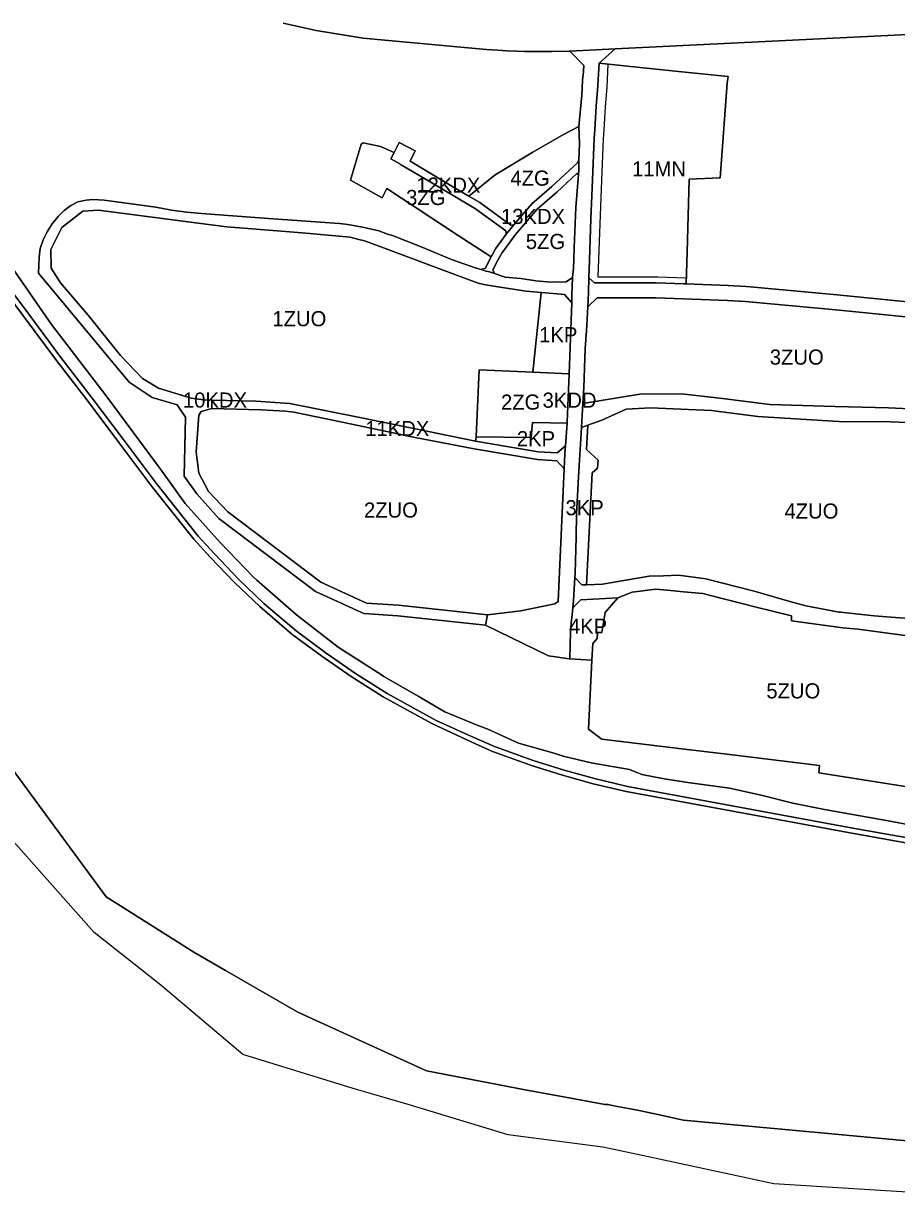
# Model space of a CAD drawing. Extents: x -300162 to -296646, y 29434 to 30761.
# Drawn here: x -298006 to -297429, y 29437 to 30215 of the extents above; entities that cross this region are included whole.
import ezdxf

# ---------------------------------------------------------------- set-up
doc = ezdxf.new("R2010")
doc.units = 0
for name, color, linetype in [('linie_rozgraniczajace', 7, 'Continuous'), ('linie_zabudowy_nieprzekraczalne', 7, 'Continuous'), ('oznaczenia_przeznaczen', 7, 'Continuous')]:
    doc.layers.add(name, color=color, linetype=linetype)

msp = doc.modelspace()

# ---------------------------------------------------------------- linework, layer by layer
at = {"layer": 'linie_rozgraniczajace'}
for points in [[(-297834.429, 30215.074), (-297812.629, 30210.261), (-297781.644, 30205.237), (-297733.747, 30200.685), (-297712.203, 30198.696), (-297699.897, 30197.649), (-297692.484, 30197.175), (-297686.228, 30196.858), (-297679.912, 30196.588), (-297674.636, 30196.456), (-297668.374, 30196.328), (-297662.056, 30196.303), (-297656.737, 30196.33), (-297645.247, 30196.578), (-297644.846, 30196.597), (-297635.515, 30186.993), (-297635.79, 30183.19), (-297636.55, 30177.47), (-297636.85, 30167.52), (-297638.96, 30146.68), (-297648.94, 30141.41), (-297669.26, 30129.69), (-297694.28, 30114.71), (-297711.654, 30100.692), (-297720.597, 30106.029), (-297737.288, 30115.896), (-297750.558, 30123.718), (-297747.058, 30130.668), (-297757.776, 30136.065), (-297761.02, 30129.622), (-297770.095, 30133.601), (-297781.551, 30136.015), (-297782.84, 30135.06), (-297790.02, 30111.23), (-297768.98, 30099.51), (-297765.93, 30105.72), (-297718.66, 30074.65), (-297696.978, 30060.544), (-297697.129, 30060.276), (-297700.683, 30053.135), (-297703.477, 30052.076), (-297706.72, 30053.03), (-297723.04, 30058.87), (-297743.15, 30067.08), (-297762.08, 30074.63), (-297765.49, 30075.52), (-297771.26, 30077.67), (-297780.95, 30080.01), (-297790.41, 30081.74), (-297793.425, 30082.092), (-297796.978, 30082.507), (-297797, 30082.51), (-297800.47, 30082.73), (-297844.24, 30085.97), (-297888.43, 30089.19), (-297898.28, 30090.18), (-297908.23, 30091.35), (-297918.66, 30093.495), (-297952.956, 30098.005), (-297960.405, 30098.422), (-297964.869, 30098.134), (-297970.39, 30097.009), (-297974.977, 30094.482), (-297979.292, 30091.17), (-297983.199, 30087.262), (-297987.293, 30082.444), (-297990.481, 30077.137), (-297993.19, 30071.771)], [(-297403, 30208.4), (-297614.92, 30198.015), (-297644.846, 30196.597), (-297645.247, 30196.578), (-297656.737, 30196.33), (-297662.056, 30196.303), (-297668.374, 30196.328), (-297674.636, 30196.456), (-297679.912, 30196.588), (-297686.228, 30196.858), (-297692.484, 30197.175), (-297699.897, 30197.649), (-297712.203, 30198.696), (-297733.747, 30200.685), (-297781.644, 30205.237), (-297812.629, 30210.261), (-297834.429, 30215.074)], [(-297408.4, 30029.57), (-297468.03, 30035.37), (-297527.92, 30041.03), (-297540.19, 30041.66), (-297567.956, 30042.662), (-297567.322, 30063.537), (-297565.85, 30111.98), (-297545.398, 30112.737), (-297540.72, 30175.38), (-297540.196, 30179.766), (-297570.75, 30182.96), (-297592.07, 30185.13), (-297625.44, 30188.57), (-297614.92, 30198.015), (-297403, 30208.4)], [(-297343.9, 29437.13), (-297510, 29447.37), (-297600.03, 29466.88), (-297623.03, 29471.65), (-297685.72, 29479.9), (-297751.84, 29500), (-297788.27, 29510.52), (-297861.05, 29532.95), (-297915.32, 29578.84), (-297959.37, 29613.67), (-298021.78, 29683.83), (-298089.26, 29768.65), (-298133.84, 29820.72), (-298172.27, 29865.83), (-298208.12, 29903.83), (-298240, 29938), (-298289.95, 30000), (-298295.47, 30008.63), (-298336.46, 30059.03), (-298349.16, 30067.38), (-298382.23, 30086.44), (-298449.27, 30117)], [(-298040.891, 30067.651), (-298006.13, 30021.4), (-297984.968, 29992.847), (-297963.49, 29964.905), (-297943.105, 29937.761), (-297921.249, 29908.659), (-297893.476, 29873.754), (-297882.793, 29861.917), (-297866.885, 29845.287), (-297849.967, 29829.235), (-297828.747, 29811.104), (-297808.797, 29796.409), (-297789.511, 29782.897), (-297768.378, 29769.617), (-297736.1, 29751.89), (-297709.716, 29739.54), (-297696.059, 29733.48), (-297670.242, 29724.237), (-297649.627, 29717.751), (-297629.329, 29712.076), (-297607.483, 29706.861), (-297458.287, 29679.362), (-297372.015, 29663.949)], [(-297372.015, 29663.949), (-297458.287, 29679.362), (-297607.483, 29706.861), (-297629.329, 29712.076), (-297649.627, 29717.751), (-297670.242, 29724.237), (-297696.059, 29733.48), (-297709.716, 29739.54), (-297736.1, 29751.89), (-297768.378, 29769.617), (-297789.511, 29782.897), (-297808.797, 29796.409), (-297828.747, 29811.104), (-297849.967, 29829.235), (-297866.885, 29845.287), (-297882.793, 29861.917), (-297893.476, 29873.754), (-297921.249, 29908.659), (-297943.105, 29937.761), (-297963.49, 29964.905), (-297984.968, 29992.847), (-298006.13, 30021.4), (-298040.891, 30067.651)], [(-297371.4, 29667.394), (-297457.662, 29682.806), (-297606.759, 29710.286), (-297628.451, 29715.465), (-297648.63, 29721.107), (-297669.127, 29727.555), (-297694.758, 29736.732), (-297708.297, 29742.74), (-297733.302, 29753.993), (-297765.58, 29771.72), (-297786.713, 29785), (-297805.999, 29798.512), (-297825.949, 29813.207), (-297847.169, 29831.338), (-297864.088, 29847.39), (-297879.995, 29864.02), (-297890.678, 29875.857), (-297918.452, 29910.762), (-297940.307, 29939.864), (-297960.692, 29967.008), (-297982.17, 29994.95), (-298003.332, 30023.503), (-298038.093, 30069.754)], [(-298038.093, 30069.754), (-298003.332, 30023.503), (-297982.17, 29994.95), (-297960.692, 29967.008), (-297940.307, 29939.864), (-297918.452, 29910.762), (-297890.678, 29875.857), (-297879.995, 29864.02), (-297864.088, 29847.39), (-297847.169, 29831.338), (-297825.949, 29813.207), (-297805.999, 29798.512), (-297786.713, 29785), (-297765.58, 29771.72), (-297733.302, 29753.993), (-297708.297, 29742.74), (-297694.758, 29736.732), (-297669.127, 29727.555), (-297648.63, 29721.107), (-297628.451, 29715.465), (-297606.759, 29710.286), (-297457.662, 29682.806), (-297371.4, 29667.394)], [(-297993.19, 30071.771), (-297995.175, 30066.143), (-297995.888, 30060.319), (-297996.354, 30049.813), (-297936.291, 29977.609), (-297921.057, 29967.524), (-297904.583, 29962.56), (-297899.052, 29954.541), (-297899.953, 29915.429), (-297891.473, 29903.717), (-297876.909, 29887.549), (-297813.085, 29839.287), (-297781.116, 29824.599), (-297758.698, 29823.144), (-297700.599, 29816.952), (-297658.966, 29796.641), (-297645.29, 29794.75), (-297644.746, 29794.714), (-297630.21, 29793.75), (-297632.44, 29748.2), (-297624.429, 29742.106), (-297623.79, 29741.62), (-297568.96, 29734.9), (-297541.11, 29731.54), (-297479.69, 29724.12), (-297480.15, 29719.3), (-297390.88, 29705.09)], [(-297415.28, 29684.09), (-297436.71, 29688.07), (-297476.37, 29695.11), (-297497.44, 29699.34), (-297518.32, 29704.43), (-297539.17, 29709.17), (-297566.8, 29712.96), (-297582.43, 29715.38), (-297597.33, 29718.21), (-297605.44, 29721.39), (-297630.67, 29725.94), (-297649.33, 29730.33), (-297654.52, 29732), (-297678.72, 29738.87), (-297699.07, 29748.16), (-297706.04, 29750.71), (-297727.47, 29759.66), (-297745.16, 29769.96), (-297767.83, 29783.02), (-297769.38, 29784.14), (-297798.04, 29802.45), (-297825.56, 29823.7), (-297851.87, 29846.63), (-297854.09, 29848.73), (-297876.1, 29871.71), (-297899.26, 29897.42), (-297915.63, 29920.03), (-297951.51, 29968.57), (-297987.76, 30015.69), (-298013.94, 30053.73)], [(-298013.94, 30053.73), (-297987.76, 30015.69), (-297951.51, 29968.57), (-297915.63, 29920.03), (-297899.26, 29897.42), (-297876.1, 29871.71), (-297854.09, 29848.73), (-297851.87, 29846.63), (-297825.56, 29823.7), (-297798.04, 29802.45), (-297769.38, 29784.14), (-297767.83, 29783.02), (-297745.16, 29769.96), (-297727.47, 29759.66), (-297706.04, 29750.71), (-297699.07, 29748.16), (-297678.72, 29738.87), (-297654.52, 29732), (-297649.33, 29730.33), (-297630.67, 29725.94), (-297605.44, 29721.39), (-297597.33, 29718.21), (-297582.43, 29715.38), (-297566.8, 29712.96), (-297539.17, 29709.17), (-297518.32, 29704.43), (-297497.44, 29699.34), (-297476.37, 29695.11), (-297436.71, 29688.07), (-297415.28, 29684.09)], [(-297409.365, 30019.617), (-297468.984, 30025.416), (-297528.647, 30031.054), (-297540.627, 30031.669), (-297569.66, 30032.716), (-297587.859, 30033.37), (-297626.691, 30033.37), (-297633.008, 30027.378), (-297632.5, 30036.85), (-297632.22, 30046.56), (-297628.59, 30043.37), (-297587.68, 30043.37), (-297569.3, 30042.71), (-297567.956, 30042.662), (-297540.19, 30041.66), (-297527.92, 30041.03), (-297468.03, 30035.37), (-297408.4, 30029.57)], [(-297415.34, 29959.91), (-297434.09, 29960.59), (-297469.36, 29961.61), (-297512.56, 29962.85), (-297543.82, 29966.76), (-297571.04, 29970), (-297598.57, 29969.77), (-297636.27, 29963.65), (-297635.7, 29974.23), (-297634.61, 29999.89), (-297633.85, 30011.62), (-297633.008, 30027.378), (-297626.691, 30033.37), (-297587.859, 30033.37), (-297569.66, 30032.716), (-297540.627, 30031.669), (-297528.647, 30031.054), (-297468.984, 30025.416), (-297409.365, 30019.617)], [(-297415.84, 29950.68), (-297438.49, 29951.58), (-297462.71, 29951.42), (-297470.73, 29951.9), (-297520.48, 29954.85), (-297551.04, 29958.99), (-297591.43, 29960.58), (-297607.53, 29959.8), (-297623.77, 29952.63), (-297632.953, 29949.162), (-297637.17, 29947.57), (-297636.27, 29963.65), (-297598.57, 29969.77), (-297571.04, 29970), (-297543.82, 29966.76), (-297512.56, 29962.85), (-297469.36, 29961.61), (-297434.09, 29960.59), (-297415.34, 29959.91)], [(-297408.23, 29820.41), (-297429.5, 29822.07), (-297443.54, 29823.17), (-297465.81, 29825.45), (-297466.67, 29825.54), (-297488.86, 29829.64), (-297499.34, 29832.7), (-297515.11, 29837.3), (-297522.95, 29839.34), (-297554.89, 29847.57), (-297573.04, 29850.01), (-297583, 29849.67), (-297592.37, 29849.35), (-297623.24, 29844.15), (-297633.904, 29843.72), (-297630.073, 29917.724), (-297626.507, 29920.883), (-297626.124, 29926.129), (-297633.851, 29933.228), (-297632.953, 29949.162), (-297623.77, 29952.63), (-297607.53, 29959.8), (-297591.43, 29960.58), (-297551.04, 29958.99), (-297520.48, 29954.85), (-297470.73, 29951.9), (-297462.71, 29951.42), (-297438.49, 29951.58), (-297415.84, 29950.68)], [(-297410.06, 29808.44), (-297454.12, 29814.24), (-297464.23, 29815.18), (-297498.34, 29819.73), (-297498.29, 29823.08), (-297521.59, 29828.95), (-297551.87, 29836.59), (-297556.92, 29837.86), (-297569.67, 29839.09), (-297580.44, 29840.12), (-297587.87, 29840.84), (-297603.61, 29838.69), (-297613, 29834.96), (-297637.516, 29833.621), (-297642.968, 29828.375), (-297642.509, 29833.348), (-297641.586, 29848.392), (-297636.864, 29843.601), (-297633.904, 29843.72), (-297623.24, 29844.15), (-297592.37, 29849.35), (-297583, 29849.67), (-297573.04, 29850.01), (-297554.89, 29847.57), (-297522.95, 29839.34), (-297515.11, 29837.3), (-297499.34, 29832.7), (-297488.86, 29829.64), (-297466.67, 29825.54), (-297465.81, 29825.45), (-297443.54, 29823.17), (-297429.5, 29822.07), (-297408.23, 29820.41)], [(-297390.88, 29705.09), (-297480.15, 29719.3), (-297479.69, 29724.12), (-297541.11, 29731.54), (-297568.96, 29734.9), (-297623.79, 29741.62), (-297624.429, 29742.106), (-297632.44, 29748.2), (-297630.21, 29793.75), (-297629.67, 29804.88), (-297626.84, 29808.14), (-297626.45, 29812), (-297623.7, 29812), (-297621.38, 29825.35), (-297613, 29834.96), (-297603.61, 29838.69), (-297587.87, 29840.84), (-297580.44, 29840.12), (-297569.67, 29839.09), (-297556.92, 29837.86), (-297551.87, 29836.59), (-297521.59, 29828.95), (-297498.29, 29823.08), (-297498.34, 29819.73), (-297464.23, 29815.18), (-297454.12, 29814.24), (-297410.06, 29808.44)], [(-298051.094, 29772.591), (-297951.586, 29637.393), (-297893.544, 29600.792), (-297872.694, 29588.579), (-297824.733, 29561.012), (-297739.61, 29522.298), (-297674.457, 29509.694), (-297644.26, 29504.153), (-297621.651, 29500.004), (-297619.547, 29499.97), (-297615.641, 29499.137), (-297605.948, 29497.334), (-297598.927, 29495.944), (-297586.654, 29493.287), (-297569.73, 29489.623), (-297495.404, 29482.761), (-297405.231, 29474.318)], [(-297405.231, 29474.318), (-297495.404, 29482.761), (-297569.73, 29489.623), (-297586.654, 29493.287), (-297598.927, 29495.944), (-297605.948, 29497.334), (-297615.641, 29499.137), (-297619.547, 29499.97), (-297621.651, 29500.004), (-297644.26, 29504.153), (-297674.457, 29509.694), (-297739.61, 29522.298), (-297824.733, 29561.012), (-297872.694, 29588.579), (-297893.544, 29600.792), (-297951.586, 29637.393), (-298051.094, 29772.591)]]:
    msp.add_lwpolyline(points, dxfattribs=at)
for points in [[(-297700.599, 29816.952), (-297699.27, 29823.85), (-297677.31, 29826.46), (-297654.8, 29831.06), (-297652.562, 29832.613), (-297648.695, 29920.41), (-297648.475, 29925.401), (-297648.176, 29930.546), (-297647.795, 29935.537), (-297646.643, 29950.629), (-297646.59, 29951.32), (-297645.4, 29983.24), (-297643.612, 30030.217), (-297643.422, 30035.194), (-297642.98, 30046.81), (-297642.52, 30052.94), (-297642.26, 30059.12), (-297641.96, 30066.73), (-297640.9, 30093.07), (-297639.188, 30115.109), (-297638.98, 30117.79), (-297638.88, 30122.65), (-297638.827, 30124.696), (-297638.55, 30135.45), (-297638.96, 30146.68), (-297636.85, 30167.52), (-297636.55, 30177.47), (-297635.79, 30183.19), (-297635.515, 30186.993), (-297644.846, 30196.597), (-297614.92, 30198.015), (-297625.44, 30188.57), (-297626.625, 30170.623), (-297627.45, 30160.14), (-297628.35, 30144.86), (-297628.78, 30138.9), (-297629.89, 30111.58), (-297630.99, 30085.7), (-297631.92, 30058.43), (-297632.22, 30046.56), (-297632.5, 30036.85), (-297633.008, 30027.378), (-297633.85, 30011.62), (-297634.61, 29999.89), (-297635.7, 29974.23), (-297636.27, 29963.65), (-297637.17, 29947.57), (-297639.2, 29915.1), (-297640.51, 29890.09), (-297640.73, 29875.48), (-297641.43, 29851.24), (-297641.586, 29848.392), (-297642.509, 29833.348), (-297642.968, 29828.375), (-297643.38, 29823.91), (-297643.91, 29818.24), (-297644.43, 29812.77), (-297644.746, 29794.714), (-297645.29, 29794.75), (-297658.966, 29796.641)], [(-297632.22, 30046.56), (-297631.92, 30058.43), (-297630.99, 30085.7), (-297629.89, 30111.58), (-297628.78, 30138.9), (-297628.35, 30144.86), (-297627.45, 30160.14), (-297626.625, 30170.623), (-297625.44, 30188.57), (-297592.07, 30185.13), (-297570.75, 30182.96), (-297540.196, 30179.766), (-297540.72, 30175.38), (-297545.398, 30112.737), (-297565.85, 30111.98), (-297567.322, 30063.537), (-297567.956, 30042.662), (-297569.3, 30042.71), (-297587.68, 30043.37), (-297628.59, 30043.37)], [(-297711.654, 30100.692), (-297694.28, 30114.71), (-297669.26, 30129.69), (-297648.94, 30141.41), (-297638.96, 30146.68), (-297638.55, 30135.45), (-297638.827, 30124.696), (-297639.93, 30122.489), (-297645.007, 30117.865), (-297656.818, 30107.107), (-297670.013, 30095.708), (-297681.919, 30081.704), (-297683.902, 30081.494), (-297704.426, 30096.379)], [(-297790.02, 30111.23), (-297782.84, 30135.06), (-297781.551, 30136.015), (-297770.095, 30133.601), (-297761.02, 30129.622), (-297763.172, 30125.347), (-297757.331, 30121.972), (-297756.93, 30121.67), (-297739.83, 30111.59), (-297723.15, 30101.73), (-297707.18, 30092.2), (-297687.177, 30077.692), (-297686.896, 30075.463), (-297694.043, 30065.76), (-297696.978, 30060.544), (-297718.66, 30074.65), (-297765.93, 30105.72), (-297768.98, 30099.51)], [(-297763.172, 30125.347), (-297761.02, 30129.622), (-297757.776, 30136.065), (-297747.058, 30130.668), (-297750.558, 30123.718), (-297737.288, 30115.896), (-297720.597, 30106.029), (-297711.654, 30100.692), (-297704.426, 30096.379), (-297683.902, 30081.494), (-297681.919, 30081.704), (-297686.896, 30075.463), (-297687.177, 30077.692), (-297707.18, 30092.2), (-297723.15, 30101.73), (-297739.83, 30111.59), (-297756.93, 30121.67), (-297757.331, 30121.972)], [(-297703.477, 30052.076), (-297700.683, 30053.135), (-297697.129, 30060.276), (-297696.978, 30060.544), (-297694.043, 30065.76), (-297686.896, 30075.463), (-297681.919, 30081.704), (-297670.013, 30095.708), (-297656.818, 30107.107), (-297645.007, 30117.865), (-297639.93, 30122.489), (-297638.827, 30124.696), (-297638.88, 30122.65), (-297638.98, 30117.79), (-297639.188, 30115.109), (-297640.113, 30115.56), (-297653.499, 30103.366), (-297666.453, 30092.176), (-297680.835, 30075.26), (-297689.836, 30063.041), (-297692.709, 30057.934), (-297695.699, 30051.928), (-297694.596, 30049.556), (-297698.02, 30050.72), (-297700.23, 30051.12)], [(-297695.699, 30051.928), (-297692.709, 30057.934), (-297689.836, 30063.041), (-297680.835, 30075.26), (-297666.453, 30092.176), (-297653.499, 30103.366), (-297640.113, 30115.56), (-297639.188, 30115.109), (-297640.9, 30093.07), (-297641.96, 30066.73), (-297642.26, 30059.12), (-297642.52, 30052.94), (-297642.98, 30046.81), (-297647.37, 30043.91), (-297657.38, 30043.81), (-297667.42, 30044.64), (-297677.36, 30046.11), (-297687.58, 30047.17), (-297694.596, 30049.556)], [(-297996.354, 30049.813), (-297995.888, 30060.319), (-297995.175, 30066.143), (-297993.19, 30071.771), (-297990.481, 30077.137), (-297987.293, 30082.444), (-297983.199, 30087.262), (-297979.292, 30091.17), (-297974.977, 30094.482), (-297970.39, 30097.009), (-297964.869, 30098.134), (-297960.405, 30098.422), (-297952.956, 30098.005), (-297918.66, 30093.495), (-297908.23, 30091.35), (-297898.28, 30090.18), (-297888.43, 30089.19), (-297844.24, 30085.97), (-297800.47, 30082.73), (-297797, 30082.51), (-297796.978, 30082.507), (-297793.425, 30082.092), (-297790.41, 30081.74), (-297780.95, 30080.01), (-297771.26, 30077.67), (-297765.49, 30075.52), (-297762.08, 30074.63), (-297743.15, 30067.08), (-297723.04, 30058.87), (-297706.72, 30053.03), (-297703.477, 30052.076), (-297700.23, 30051.12), (-297698.02, 30050.72), (-297694.596, 30049.556), (-297687.58, 30047.17), (-297677.36, 30046.11), (-297667.42, 30044.64), (-297657.38, 30043.81), (-297647.37, 30043.91), (-297642.98, 30046.81), (-297643.422, 30035.194), (-297643.612, 30030.217), (-297648.399, 30035.672), (-297650.57, 30035.88), (-297663.918, 30036.992), (-297673.73, 30037.81), (-297692.53, 30040.62), (-297701.73, 30042.3), (-297705.44, 30043.24), (-297730.44, 30052.46), (-297771.54, 30067.75), (-297780.63, 30071.16), (-297785.32, 30072.33), (-297790.1, 30073.53), (-297821.87, 30076.4), (-297871.66, 30080.28), (-297890.64, 30082.75), (-297956.72, 30091.44), (-297966.89, 30090.83), (-297980.77, 30079.92), (-297988.1, 30065.35), (-297987.94, 30053.01), (-297981.81, 30043.29), (-297963.53, 30021.96), (-297941.98, 29995.4), (-297927.48, 29980.1), (-297916.96, 29973.6), (-297895.32, 29967.08), (-297886.98, 29965.97), (-297881.553, 29965.847), (-297881.68, 29960.24), (-297888.6, 29958.36), (-297890.27, 29955.82), (-297891.98, 29931.61), (-297890.23, 29917.39), (-297883.94, 29905.46), (-297871.11, 29891.94), (-297809.47, 29845.33), (-297779.37, 29831.5), (-297758.1, 29830.12), (-297699.27, 29823.85), (-297700.599, 29816.952), (-297758.698, 29823.144), (-297781.116, 29824.599), (-297813.085, 29839.287), (-297876.909, 29887.549), (-297891.473, 29903.717), (-297899.953, 29915.429), (-297899.052, 29954.541), (-297904.583, 29962.56), (-297921.057, 29967.524), (-297936.291, 29977.609)], [(-297988.1, 30065.35), (-297980.77, 30079.92), (-297966.89, 30090.83), (-297956.72, 30091.44), (-297890.64, 30082.75), (-297871.66, 30080.28), (-297821.87, 30076.4), (-297790.1, 30073.53), (-297785.32, 30072.33), (-297780.63, 30071.16), (-297771.54, 30067.75), (-297730.44, 30052.46), (-297705.44, 30043.24), (-297701.73, 30042.3), (-297692.53, 30040.62), (-297673.73, 30037.81), (-297663.918, 30036.992), (-297669.22, 29984.307), (-297704.77, 29985.9), (-297706.75, 29941.41), (-297707.29, 29938.56), (-297756.74, 29948.75), (-297784.87, 29954.55), (-297830.15, 29963.61), (-297852.44, 29965.19), (-297881.553, 29965.847), (-297886.98, 29965.97), (-297895.32, 29967.08), (-297916.96, 29973.6), (-297927.48, 29980.1), (-297941.98, 29995.4), (-297963.53, 30021.96), (-297981.81, 30043.29), (-297987.94, 30053.01)], [(-297669.22, 29984.307), (-297663.918, 30036.992), (-297650.57, 30035.88), (-297648.399, 30035.672), (-297643.612, 30030.217), (-297645.4, 29983.24)], [(-297706.75, 29941.41), (-297704.77, 29985.9), (-297669.22, 29984.307), (-297645.4, 29983.24), (-297646.59, 29951.32), (-297646.643, 29950.629), (-297669.514, 29950.993), (-297670.412, 29941.138)], [(-297881.68, 29960.24), (-297881.553, 29965.847), (-297852.44, 29965.19), (-297830.15, 29963.61), (-297784.87, 29954.55), (-297756.74, 29948.75), (-297707.29, 29938.56), (-297665.76, 29931.662), (-297653.166, 29930.862), (-297647.795, 29935.537), (-297648.176, 29930.546), (-297648.475, 29925.401), (-297648.695, 29920.41), (-297653.465, 29925.718), (-297666.26, 29926.53), (-297708.04, 29933.47), (-297751.71, 29942.04), (-297757.47, 29943.25), (-297799.68, 29952.1), (-297827.51, 29957.72), (-297832.85, 29958.56), (-297849.15, 29959.47)], [(-297891.98, 29931.61), (-297890.27, 29955.82), (-297888.6, 29958.36), (-297881.68, 29960.24), (-297849.15, 29959.47), (-297832.85, 29958.56), (-297827.51, 29957.72), (-297799.68, 29952.1), (-297757.47, 29943.25), (-297751.71, 29942.04), (-297708.04, 29933.47), (-297666.26, 29926.53), (-297653.465, 29925.718), (-297648.695, 29920.41), (-297652.562, 29832.613), (-297654.8, 29831.06), (-297677.31, 29826.46), (-297699.27, 29823.85), (-297758.1, 29830.12), (-297779.37, 29831.5), (-297809.47, 29845.33), (-297871.11, 29891.94), (-297883.94, 29905.46), (-297890.23, 29917.39)], [(-297707.29, 29938.56), (-297706.75, 29941.41), (-297670.412, 29941.138), (-297669.514, 29950.993), (-297646.643, 29950.629), (-297647.795, 29935.537), (-297653.166, 29930.862), (-297665.76, 29931.662)], [(-297641.586, 29848.392), (-297641.43, 29851.24), (-297640.73, 29875.48), (-297640.51, 29890.09), (-297639.2, 29915.1), (-297637.17, 29947.57), (-297632.953, 29949.162), (-297633.851, 29933.228), (-297626.124, 29926.129), (-297626.507, 29920.883), (-297630.073, 29917.724), (-297633.904, 29843.72), (-297636.864, 29843.601)], [(-297644.746, 29794.714), (-297644.43, 29812.77), (-297643.91, 29818.24), (-297643.38, 29823.91), (-297642.968, 29828.375), (-297637.516, 29833.621), (-297613, 29834.96), (-297621.38, 29825.35), (-297623.7, 29812), (-297626.45, 29812), (-297626.84, 29808.14), (-297629.67, 29804.88), (-297630.21, 29793.75)]]:
    msp.add_lwpolyline(points, close=True, dxfattribs=at)
at = {"layer": 'linie_zabudowy_nieprzekraczalne'}
for points in [[(-297619.679, 30187.968), (-297620.472, 30172.756), (-297621.463, 30159.736), (-297622.363, 30144.468), (-297622.789, 30138.562), (-297623.895, 30111.342), (-297626.379, 30047.37)], [(-297626.379, 30047.37), (-297586.726, 30047.37), (-297567.834, 30046.69)]]:
    msp.add_lwpolyline(points, dxfattribs=at)

# ---------------------------------------------------------------- texts
at = {"layer": 'oznaczenia_przeznaczen'}
for s, p in [('11MN', (-297603.708114, 30113.750001)), ('4ZG', (-297684.166303, 30107.600001)), ('12KDX', (-297746.373679, 30103.000001)), ('3ZG', (-297753.150303, 30094.810001)), ('13KDX', (-297690.387679, 30082.290001)), ('5ZG', (-297673.976303, 30065.700001)), ('1ZUO', (-297841.602571, 30014.640001)), ('1KP', (-297665.128536, 30004.040001)), ('3ZUO', (-297512.576596, 29989.250001)), ('10KDX', (-297900.753145, 29960.840001)), ('2ZG', (-297690.376303, 29959.490001)), ('3KDD', (-297662.881425, 29960.750001)), ('11KDX', (-297780.163655, 29942.020001)), ('2KP', (-297679.888561, 29935.280001)), ('2ZUO', (-297781.012596, 29888.090001)), ('3KP', (-297647.712561, 29889.640001)), ('4ZUO', (-297502.862596, 29887.420001)), ('4KP', (-297645.438561, 29811.260001)), ('5ZUO', (-297514.882596, 29768.500001))]:
    msp.add_text(s, height=10, dxfattribs=at).set_placement(p)

doc.saveas('drawing.dxf')
